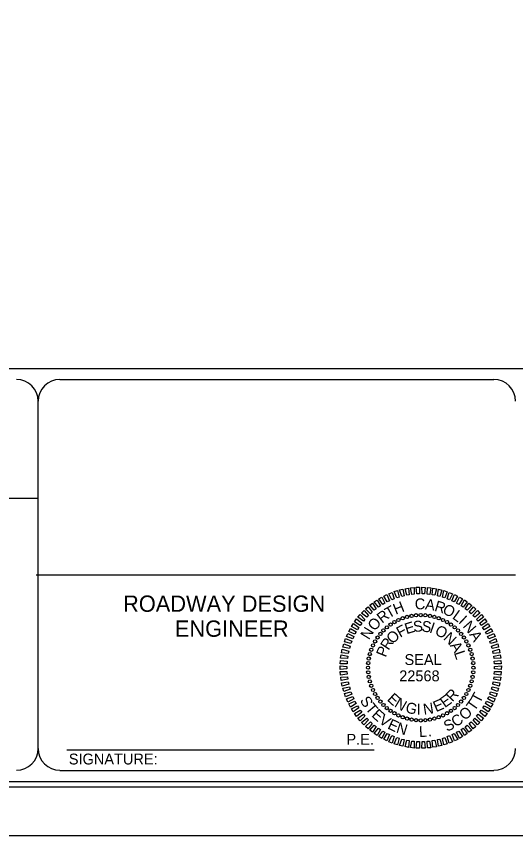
# Model space of a CAD drawing. Extents: x 2128934 to 2134034, y 641595 to 644895.
# Drawn here: x 2132705 to 2133394, y 641595 to 642727 of the extents above; entities that cross this region are included whole.
import ezdxf

# ---------------------------------------------------------------- set-up
doc = ezdxf.new("R2010")
doc.units = 0
for name, color, linetype in [('Sheet PE Seal Cell', 7, 'Continuous'), ('Sheet Plot Border Inside CELL', 7, 'Continuous'), ('Sheet Plot Border Outside CELL', 7, 'Continuous'), ('Sheet Title CELL', 7, 'Continuous')]:
    doc.layers.add(name, color=color, linetype=linetype)

msp = doc.modelspace()

# ---------------------------------------------------------------- linework, layer by layer
at = {"layer": 'Sheet PE Seal Cell'}
for points in [[(2133223.3, 641921), (2133219.2, 641929.3), (2133223.7, 641931.1), (2133226.5, 641922.3)], [(2133230, 641923.5), (2133226.4, 641932.2), (2133231, 641933.6), (2133233.2, 641924.6)], [(2133236.8, 641925.6), (2133233.8, 641934.5), (2133238.5, 641935.6), (2133240.1, 641926.4)], [(2133243.7, 641927.2), (2133241.4, 641936.2), (2133246.2, 641937), (2133247.1, 641927.8)], [(2133250.7, 641928.3), (2133249, 641937.5), (2133253.9, 641937.9), (2133254.1, 641928.7)], [(2133257.8, 641928.9), (2133256.8, 641938.2), (2133261.6, 641938.3), (2133261.2, 641929)], [(2133264.9, 641929), (2133264.6, 641938.4), (2133269.4, 641938.1), (2133268.4, 641928.9)], [(2133272, 641928.6), (2133272.3, 641938), (2133277.1, 641937.4), (2133275.5, 641928.3)], [(2133279.1, 641927.8), (2133280, 641937.1), (2133284.8, 641936.2), (2133282.5, 641927.2)], [(2133286.1, 641926.4), (2133287.7, 641935.6), (2133292.3, 641934.4), (2133289.4, 641925.6)], [(2133293, 641924.6), (2133295.2, 641933.7), (2133299.8, 641932.1), (2133296.2, 641923.5)], [(2133299.7, 641922.2), (2133302.5, 641931.2), (2133307, 641929.3), (2133302.9, 641921)], [(2133204.7, 641910.6), (2133198.8, 641918), (2133202.9, 641920.6), (2133207.5, 641912.6)], [(2133210.6, 641914.5), (2133205.3, 641922.2), (2133209.6, 641924.6), (2133213.6, 641916.2)], [(2133216.9, 641918), (2133212.1, 641926), (2133216.5, 641928.1), (2133219.9, 641919.5)], [(2133306.2, 641919.5), (2133309.7, 641928.2), (2133314, 641926), (2133309.3, 641918)], [(2133312.6, 641916.2), (2133316.6, 641924.7), (2133320.8, 641922.2), (2133315.6, 641914.5)], [(2133318.7, 641912.5), (2133323.3, 641920.7), (2133327.3, 641917.9), (2133321.5, 641910.6)], [(2133193.6, 641901.7), (2133186.8, 641908.2), (2133190.5, 641911.3), (2133196.1, 641904)], [(2133199, 641906.4), (2133192.7, 641913.3), (2133196.5, 641916.2), (2133201.7, 641908.5)], [(2133324.5, 641908.5), (2133329.7, 641916.3), (2133333.5, 641913.2), (2133327.2, 641906.4)], [(2133330, 641904), (2133335.8, 641911.4), (2133339.3, 641908.1), (2133332.6, 641901.7)], [(2133183.9, 641891.3), (2133176.3, 641896.7), (2133179.5, 641900.4), (2133186.1, 641893.9)], [(2133188.6, 641896.7), (2133181.4, 641902.6), (2133184.8, 641906.1), (2133190.9, 641899.1)], [(2133335.2, 641899.1), (2133341.5, 641906.1), (2133344.8, 641902.6), (2133337.6, 641896.7)], [(2133340.1, 641893.9), (2133346.8, 641900.5), (2133349.8, 641896.7), (2133342.3, 641891.3)], [(2133175.7, 641879.6), (2133167.4, 641884), (2133170.1, 641888.1), (2133177.5, 641882.6)], [(2133179.6, 641885.6), (2133171.6, 641890.5), (2133174.5, 641894.4), (2133181.6, 641888.4)], [(2133344.6, 641888.4), (2133351.7, 641894.4), (2133354.5, 641890.5), (2133346.6, 641885.6)], [(2133348.6, 641882.5), (2133356.2, 641888.1), (2133358.7, 641883.9), (2133350.5, 641879.6)], [(2133169.3, 641867), (2133160.4, 641870.1), (2133162.5, 641874.5), (2133170.6, 641870.1)], [(2133172.3, 641873.4), (2133163.7, 641877.2), (2133166, 641881.4), (2133173.9, 641876.5)], [(2133352.3, 641876.4), (2133360.2, 641881.4), (2133362.4, 641877.1), (2133353.9, 641873.4)], [(2133355.5, 641870.1), (2133363.8, 641874.5), (2133365.7, 641870.1), (2133357, 641867)], [(2133166.7, 641860.3), (2133157.7, 641862.9), (2133159.4, 641867.4), (2133167.8, 641863.6)], [(2133358.3, 641863.5), (2133366.8, 641867.4), (2133368.4, 641862.8), (2133359.5, 641860.3)], [(2133163, 641846.6), (2133153.7, 641847.8), (2133154.8, 641852.6), (2133163.7, 641849.9)], [(2133164.6, 641853.5), (2133155.4, 641855.4), (2133156.9, 641860), (2133165.5, 641856.8)], [(2133360.6, 641856.8), (2133369.4, 641860.1), (2133370.7, 641855.4), (2133361.6, 641853.5)], [(2133362.5, 641849.9), (2133371.4, 641852.6), (2133372.4, 641847.8), (2133363.2, 641846.6)], [(2133161.9, 641839.6), (2133152.5, 641840.2), (2133153.3, 641844.9), (2133162.3, 641843)], [(2133363.8, 641842.9), (2133373, 641844.9), (2133373.6, 641840.1), (2133364.3, 641839.6)], [(2133161.1, 641825.4), (2133151.8, 641824.6), (2133151.9, 641829.5), (2133161.1, 641828.8)], [(2133161.3, 641832.5), (2133151.9, 641832.4), (2133152.3, 641837.2), (2133161.5, 641835.9)], [(2133364.7, 641835.9), (2133373.9, 641837.2), (2133374.2, 641832.4), (2133364.9, 641832.5)], [(2133365, 641828.8), (2133374.4, 641829.5), (2133374.3, 641824.6), (2133365.1, 641825.3)], [(2133161.5, 641818.2), (2133152.2, 641816.9), (2133152, 641821.7), (2133161.2, 641821.7)], [(2133364.9, 641821.7), (2133374.3, 641821.7), (2133373.9, 641816.9), (2133364.7, 641818.2)], [(2133162.4, 641811.2), (2133153.2, 641809.2), (2133152.6, 641814), (2133161.9, 641814.6)], [(2133163.7, 641804.2), (2133154.7, 641801.6), (2133153.8, 641806.3), (2133163, 641807.5)], [(2133363.2, 641807.5), (2133372.5, 641806.3), (2133371.4, 641801.6), (2133362.5, 641804.2)], [(2133364.3, 641814.6), (2133373.6, 641814), (2133372.9, 641809.2), (2133363.8, 641811.2)], [(2133165.6, 641797.3), (2133156.8, 641794.1), (2133155.5, 641798.7), (2133164.6, 641800.6)], [(2133167.9, 641790.6), (2133159.3, 641786.7), (2133157.8, 641791.3), (2133166.7, 641793.8)], [(2133359.5, 641793.8), (2133368.5, 641791.3), (2133366.8, 641786.7), (2133358.3, 641790.6)], [(2133361.6, 641800.6), (2133370.7, 641798.7), (2133369.3, 641794.1), (2133360.6, 641797.3)], [(2133170.6, 641784), (2133162.4, 641779.6), (2133160.5, 641784), (2133169.2, 641787.2)], [(2133356.9, 641787.2), (2133365.7, 641784), (2133363.7, 641779.6), (2133355.6, 641784)], [(2133173.9, 641777.7), (2133166, 641772.7), (2133163.8, 641777), (2133172.2, 641780.7)], [(2133177.5, 641771.6), (2133170, 641766), (2133167.5, 641770.2), (2133175.7, 641774.5)], [(2133350.5, 641774.5), (2133358.8, 641770.1), (2133356.1, 641766.1), (2133348.7, 641771.6)], [(2133353.9, 641780.7), (2133362.5, 641777), (2133360.1, 641772.7), (2133352.3, 641777.7)], [(2133181.6, 641765.8), (2133174.5, 641759.7), (2133171.7, 641763.7), (2133179.6, 641768.5)], [(2133186.1, 641760.2), (2133179.4, 641753.7), (2133176.3, 641757.4), (2133183.9, 641762.8)], [(2133342.3, 641762.8), (2133349.9, 641757.4), (2133346.7, 641753.7), (2133340.1, 641760.2)], [(2133346.6, 641768.5), (2133354.6, 641763.6), (2133351.6, 641759.7), (2133344.6, 641765.7)], [(2133190.9, 641755), (2133184.7, 641748), (2133181.4, 641751.6), (2133188.5, 641757.5)], [(2133196.1, 641750.2), (2133190.4, 641742.7), (2133186.9, 641746), (2133193.6, 641752.4)], [(2133201.7, 641745.7), (2133196.5, 641737.9), (2133192.7, 641740.9), (2133199, 641747.8)], [(2133327.2, 641747.8), (2133333.5, 641740.9), (2133329.6, 641737.9), (2133324.5, 641745.6)], [(2133332.6, 641752.4), (2133339.4, 641746), (2133335.7, 641742.8), (2133330.1, 641750.1)], [(2133337.6, 641757.5), (2133344.8, 641751.5), (2133341.4, 641748.1), (2133335.3, 641755)], [(2133207.5, 641741.6), (2133202.9, 641733.4), (2133198.9, 641736.2), (2133204.6, 641743.5)], [(2133213.6, 641737.9), (2133209.5, 641729.5), (2133205.4, 641732), (2133210.6, 641739.6)], [(2133315.5, 641739.6), (2133320.8, 641731.9), (2133316.6, 641729.5), (2133312.6, 641737.9)], [(2133321.5, 641743.5), (2133327.3, 641736.2), (2133323.3, 641733.5), (2133318.7, 641741.6)], [(2133219.9, 641734.7), (2133216.5, 641726), (2133212.2, 641728.2), (2133216.8, 641736.2)], [(2133226.5, 641731.9), (2133223.6, 641723), (2133219.2, 641724.9), (2133223.3, 641733.2)], [(2133233.2, 641729.6), (2133231, 641720.5), (2133226.4, 641722.1), (2133229.9, 641730.6)], [(2133240.1, 641727.7), (2133238.5, 641718.5), (2133233.8, 641719.7), (2133236.8, 641728.5)], [(2133247.1, 641726.4), (2133246.1, 641717), (2133241.4, 641718), (2133243.7, 641726.9)], [(2133254.1, 641725.5), (2133253.9, 641716.1), (2133249.1, 641716.7), (2133250.7, 641725.8)], [(2133261.2, 641725.1), (2133261.6, 641715.8), (2133256.8, 641716), (2133257.8, 641725.2)], [(2133268.4, 641725.2), (2133269.4, 641715.9), (2133264.5, 641715.8), (2133264.9, 641725.1)], [(2133275.4, 641725.8), (2133277.1, 641716.6), (2133272.3, 641716.2), (2133272, 641725.5)], [(2133282.5, 641727), (2133284.8, 641717.9), (2133280, 641717.1), (2133279.1, 641726.3)], [(2133289.4, 641728.5), (2133292.4, 641719.7), (2133287.6, 641718.6), (2133286.1, 641727.7)], [(2133296.2, 641730.6), (2133299.8, 641722), (2133295.1, 641720.5), (2133293, 641729.5)], [(2133302.9, 641733.2), (2133307, 641724.8), (2133302.5, 641723), (2133299.7, 641731.9)], [(2133309.3, 641736.2), (2133314.1, 641728.1), (2133309.7, 641726), (2133306.3, 641734.7)]]:
    msp.add_lwpolyline(points, close=True, dxfattribs=at)
for centre in [(2133232.3, 641893), (2133238.2, 641895.4), (2133244.3, 641897.3), (2133250.5, 641898.7), (2133256.7, 641899.5), (2133263.1, 641899.8), (2133269.4, 641899.5), (2133275.7, 641898.7), (2133281.9, 641897.3), (2133288, 641895.4), (2133293.8, 641893), (2133216.3, 641882.8), (2133221.4, 641886.7), (2133226.7, 641890.1), (2133299.5, 641890.1), (2133304.8, 641886.7), (2133309.9, 641882.8), (2133207.4, 641873.8), (2133211.6, 641878.5), (2133314.5, 641878.5), (2133318.8, 641873.8), (2133200.1, 641863.4), (2133203.5, 641868.8), (2133322.7, 641868.8), (2133326.1, 641863.4), (2133194.7, 641851.9), (2133197.2, 641857.8), (2133329, 641857.8), (2133331.5, 641851.9), (2133191.4, 641839.7), (2133192.8, 641845.9), (2133333.4, 641845.9), (2133334.7, 641839.7), (2133190.3, 641827.1), (2133190.6, 641833.4), (2133335.6, 641833.4), (2133335.8, 641827.1), (2133190.6, 641820.7), (2133191.4, 641814.4), (2133334.7, 641814.4), (2133335.6, 641820.7), (2133192.8, 641808.2), (2133194.7, 641802.2), (2133331.5, 641802.2), (2133333.4, 641808.2), (2133197.2, 641796.3), (2133329, 641796.3), (2133200.1, 641790.7), (2133203.5, 641785.3), (2133207.4, 641780.3), (2133318.8, 641780.3), (2133322.7, 641785.3), (2133326.1, 641790.7), (2133211.6, 641775.6), (2133216.3, 641771.3), (2133309.9, 641771.3), (2133314.5, 641775.6), (2133221.4, 641767.5), (2133226.7, 641764.1), (2133232.3, 641761.1), (2133238.2, 641758.7), (2133244.3, 641756.8), (2133281.9, 641756.8), (2133288, 641758.7), (2133293.8, 641761.1), (2133299.5, 641764.1), (2133304.8, 641767.5), (2133250.5, 641755.4), (2133256.7, 641754.6), (2133263.1, 641754.3), (2133269.4, 641754.6), (2133275.7, 641755.4)]:
    msp.add_circle(centre, 2.25, dxfattribs=at)
at = {"layer": 'Sheet Plot Border Inside CELL'}
msp.add_lwpolyline([(2128972.8, 641662.5), (2133972.3, 641662.5), (2133972.3, 644827.8), (2128972.8, 644827.8)], close=True, dxfattribs=at)
at = {"layer": 'Sheet Plot Border Outside CELL'}
msp.add_lwpolyline([(2128933.8, 641595.1), (2134033.8, 641595.1), (2134033.8, 644895.1), (2128933.8, 644895.1)], close=True, dxfattribs=at)
at = {"layer": 'Sheet Title CELL'}
for p, q in [((2129629.8, 642240.2), (2133889.8, 642240.2)), ((2132764.8, 642225.2), (2133364.1, 642225.2)), ((2132734.8, 641715.1), (2132734.8, 642195.1)), ((2132734.8, 642060.9), (2131819.8, 642060.9)), ((2132732.1, 641955.2), (2133394.1, 641955.2)), ((2132774.5, 641713.5), (2133199, 641713.5))]:
    msp.add_line(p, q, dxfattribs=at)
for points in [[(2132764.8, 641685.2), (2133364.1, 641685.2)], [(2129464.8, 641670.1), (2133904.8, 641670.1)]]:
    msp.add_lwpolyline(points, dxfattribs=at)
for centre, start, end in [((2132704.8, 642195.3), 0, 90), ((2132764.8, 642195.3), 90, 180), ((2133364.1, 642195.2), 0, 90), ((2132704.8, 641715.3), 270, 360), ((2132764.8, 641715.3), 180, 270), ((2133364.1, 641715.3), 270, 360)]:
    msp.add_arc(centre, 30, start, end, dxfattribs=at)

# ---------------------------------------------------------------- texts
at = {"layer": 'Sheet PE Seal Cell'}
for s, rotation, p in [('H', 21.601, (2133228.5, 641900.1)), ('C', 1.9618, (2133255.1, 641907.5)), ('A', 352.4568, (2133268.5, 641907.7)), ('R', 343.4093, (2133281.1, 641905.8)), ('T', 29.3903, (2133218.9, 641894.7)), ('O', 335.2006, (2133292.1, 641902.5)), ('L', 324.4755, (2133305.7, 641895.7)), ('O', 48.3241, (2133199.4, 641876.8)), ('R', 37.5989, (2133209.7, 641887.7)), ('I', 317.0103, (2133314.2, 641889.6)), ('F', 28.6639, (2133234.6, 641868.3)), ('E', 16.986, (2133243.5, 641873.2)), ('S', 5.2237, (2133253.3, 641876.3)), ('S', 353.2648, (2133263.7, 641877.2)), ('I', 341.3058, (2133274.1, 641876)), ('O', 332.5504, (2133281.4, 641873.7)), ('N', 311.0704, (2133320.4, 641884)), ('N', 58.5345, (2133191.6, 641864.7)), ('O', 44.4727, (2133224.4, 641859)), ('N', 316.7416, (2133293.4, 641867)), ('A', 300.8599, (2133329.6, 641872.9)), ('R', 56.5721, (2133218.6, 641850.2)), ('P', 68.3344, (2133214.8, 641840.6)), ('A', 301.6915, (2133302.8, 641857.7)), ('L', 288.3556, (2133308.8, 641847.8)), ('R', 47.043, (2133307, 641779)), ('T', 62.3829, (2133344.7, 641776.7)), ('S', 302.1713, (2133178.5, 641781.9)), ('E', 317.8506, (2133215.7, 641782.5)), ('N', 329.6129, (2133225.7, 641773.8)), ('E', 23.5185, (2133284.2, 641765.5)), ('E', 35.2807, (2133296.3, 641771.1)), ('T', 54.5936, (2133337.1, 641766.1)), ('T', 310.2847, (2133185.8, 641770.4)), ('E', 318.0739, (2133194.2, 641760.4)), ('G', 344.6629, (2133240.9, 641765.9)), ('I', 359.713, (2133257.5, 641762.2)), ('N', 8.4684, (2133267.5, 641762.1)), ('O', 43.8685, (2133324.5, 641753.4)), ('V', 326.0538, (2133204.1, 641751.5)), ('C', 34.3634, (2133311.5, 641744.3)), ('E', 334.739, (2133216.2, 641743.5)), ('N', 342.7189, (2133228.2, 641737.8)), ('S', 26.2501, (2133299.3, 641738.3)), ('L', 2.8157, (2133261, 641731.2)), ('.', 10.2808, (2133273.5, 641731.8))]:
    msp.add_text(s, height=15, rotation=rotation, dxfattribs=at).set_placement(p)
for s, p in [('SEAL', (2133240.7, 641830.8)), ('22568', (2133233.4, 641808.3))]:
    msp.add_text(s, height=15, dxfattribs=at).set_placement(p)
at = {"layer": 'Sheet Title CELL'}
for s, height, p in [('ROADWAY DESIGN', 22.498, (2132852.1, 641904.3)), ('ENGINEER', 22.5, (2132923.6, 641869.8)), ('P.E.', 15, (2133160.5, 641720.7)), ('SIGNATURE:', 15, (2132777.2, 641693.4))]:
    msp.add_text(s, height=height, rotation=360, dxfattribs=at).set_placement(p)

doc.saveas('drawing.dxf')
